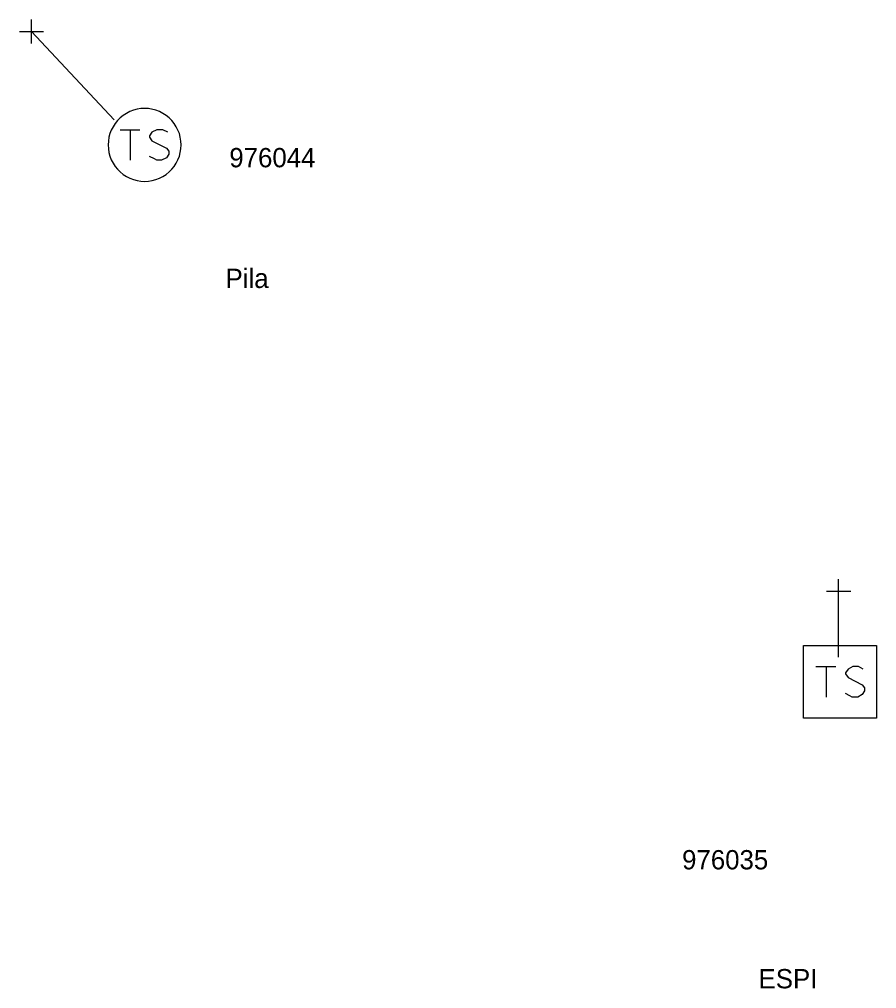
# Model space of a CAD drawing. Extents: x -788458 to -786145, y -1154772 to -1152372.
# Drawn here: x -787533.9 to -787489.5, y -1154001.3 to -1153951.1 of the extents above; entities that cross this region are included whole.
import ezdxf

# ---------------------------------------------------------------- set-up
doc = ezdxf.new("R2010")
doc.units = 0
for name, color, linetype in [('Vrstva 1', 7, 'Continuous'), ('Vrstva 25', 7, 'Continuous'), ('Vrstva 26', 7, 'Continuous'), ('Vrstva 27', 7, 'Continuous'), ('Vrstva 34', 7, 'Continuous'), ('Vrstva 59', 7, 'Continuous'), ('Vrstva 6', 7, 'Continuous')]:
    doc.layers.add(name, color=color, linetype=linetype)

# ---------------------------------------------------------------- blocks, each defined once
blk = doc.blocks.new('NN800')
at = {"layer": 'Vrstva 1'}
for points in [[(-0.442, 0.442), (0.442, -0.442)], [(-0.442, -0.442), (0.442, 0.442)]]:
    blk.add_lwpolyline(points, dxfattribs=at)
blk = doc.blocks.new('NN640')
at = {"layer": 'Vrstva 6'}
for points in [[(-1.89, 1.889), (1.889, 1.889)], [(-1.89, -1.89), (-1.89, 1.889)], [(1.889, 1.889), (1.889, -1.89)], [(-1.26, 0.787), (-0.221, 0.787)], [(-0.725, 0.787), (-0.725, -0.788)], [(1.197, 0.661), (0.945, 0.787), (0.661, 0.787), (0.409, 0.661), (0.283, 0.472), (0.283, 0.409), (0.409, 0.22), (1.133, -0.158), (1.259, -0.316), (1.259, -0.473), (1.133, -0.662), (0.913, -0.788), (0.629, -0.788), (0.503, -0.725), (0.283, -0.599)], [(1.889, -1.89), (-1.89, -1.89)]]:
    blk.add_lwpolyline(points, dxfattribs=at)
blk = doc.blocks.new('NN610')
at = {"layer": 'Vrstva 6'}
for points in [[(1.883, -0.001), (1.872, 0.196), (1.841, 0.392), (1.79, 0.583), (1.718, 0.768), (1.629, 0.943), (1.521, 1.109), (1.397, 1.263), (1.257, 1.403), (1.103, 1.527), (0.937, 1.635), (0.761, 1.725), (0.577, 1.796), (0.19, 1.878), (0.19, 1.878), (-0.007, 1.889), (-0.205, 1.878), (-0.401, 1.847), (-0.591, 1.796), (-0.777, 1.725), (-0.952, 1.635), (-1.118, 1.527), (-1.272, 1.403), (-1.412, 1.263), (-1.536, 1.109), (-1.644, 0.943), (-1.734, 0.768), (-1.805, 0.583), (-1.856, 0.392), (-1.887, 0.196), (-1.898, -0.001), (-1.887, -0.199), (-1.856, -0.395), (-1.805, -0.585), (-1.734, -0.77), (-1.644, -0.946), (-1.536, -1.112), (-1.411, -1.266), (-1.272, -1.405), (-1.118, -1.53), (-0.952, -1.638), (-0.776, -1.728), (-0.591, -1.799), (-0.401, -1.85), (-0.205, -1.881), (-0.007, -1.892), (0.19, -1.881), (0.385, -1.85), (0.577, -1.799), (0.761, -1.728), (0.937, -1.638), (1.103, -1.53), (1.257, -1.405), (1.397, -1.266), (1.521, -1.112), (1.629, -0.946), (1.718, -0.77), (1.79, -0.585), (1.841, -0.395), (1.872, -0.199), (1.883, -0.001)], [(-1.269, 0.782), (-0.261, 0.782)], [(-0.765, 0.782), (-0.765, -0.792)], [(1.188, 0.656), (0.936, 0.782), (0.621, 0.782), (0.369, 0.656), (0.243, 0.468), (0.243, 0.404), (0.369, 0.216), (1.125, -0.162), (1.251, -0.32), (1.251, -0.478), (1.125, -0.666), (0.873, -0.792), (0.621, -0.792), (0.495, -0.73), (0.243, -0.604)]]:
    blk.add_lwpolyline(points, dxfattribs=at)

msp = doc.modelspace()

# ---------------------------------------------------------------- linework, layer by layer
at = {"layer": 'Vrstva 59'}
for points in [[(-787529.015, -1153956.285), (-787533.3, -1153951.7)], [(-787491.489, -1153984.125), (-787491.489, -1153980.712)]]:
    msp.add_lwpolyline(points, dxfattribs=at)

# ---------------------------------------------------------------- block references
at = {"layer": 'Vrstva 25'}
for name, p in [('NN610', (-787527.43, -1153957.58)), ('NN640', (-787491.41, -1153985.41))]:
    msp.add_blockref(name, p, dxfattribs=at)
at = {"layer": 'Vrstva 34'}
for p, rotation in [((-787533.3, -1153951.7), 45.00000009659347), ((-787491.489, -1153980.712), 44.99999995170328)]:
    msp.add_blockref('NN800', p, dxfattribs=dict(at, rotation=rotation))

# ---------------------------------------------------------------- texts
at = {"layer": 'Vrstva 26'}
for s, p in [('976044', (-787523.051, -1153958.741)), ('976035', (-787499.597, -1153995.132))]:
    msp.add_text(s, height=1, dxfattribs=at).set_placement(p)
at = {"layer": 'Vrstva 27'}
for s, p in [('Pila', (-787523.246, -1153964.998)), ('ESPI', (-787495.635, -1154001.298))]:
    msp.add_text(s, height=1, dxfattribs=at).set_placement(p)

doc.saveas('drawing.dxf')
